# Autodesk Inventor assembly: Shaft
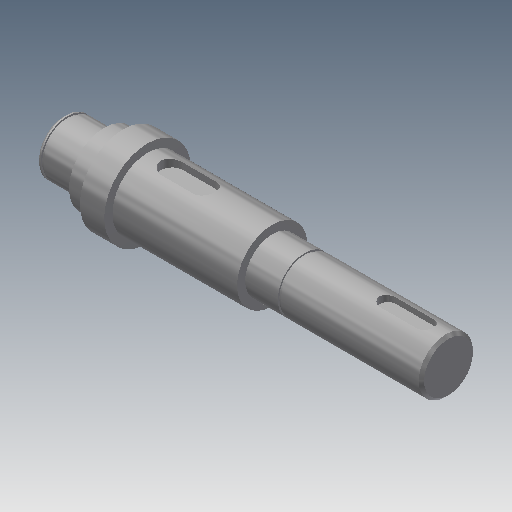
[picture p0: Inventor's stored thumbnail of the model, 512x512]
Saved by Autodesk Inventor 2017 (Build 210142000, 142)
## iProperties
Created: 2019-02
Part Number: Shaft
Document SubType Name: Assembly
Designer: user
Mass: 468.646 g
Surface Area: 121.458 cm^2
Volume: 59.7002 cm^3
Density: 7.85 g/cm^3
ClientObjectVersion: 1
Author: user
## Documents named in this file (2)
- C:\Users\user\Documents\EIA\Cursos\Diseño asistido por computador\Clase 7 Dynamic simulation\Ensamble reductor de velocidad\Ensamble\Design Accelerator\Shaft2.iam
- C:\Users\user\Documents\EIA\Cursos\Diseño asistido por computador\Clase 7 Dynamic simulation\Ensamble reductor de velocidad\Ensamble\Design Accelerator\Shaft2.ipt
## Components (1 placed, 1 different names)
1. Shaft:1
